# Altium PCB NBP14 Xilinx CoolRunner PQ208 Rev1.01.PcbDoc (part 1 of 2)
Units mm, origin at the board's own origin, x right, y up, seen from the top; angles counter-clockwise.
Board outline 69 x 80.99 mm, 2 copper layers (Top Layer, Bottom Layer); 33 components, 179 nets, 478 pads, 87 vias.
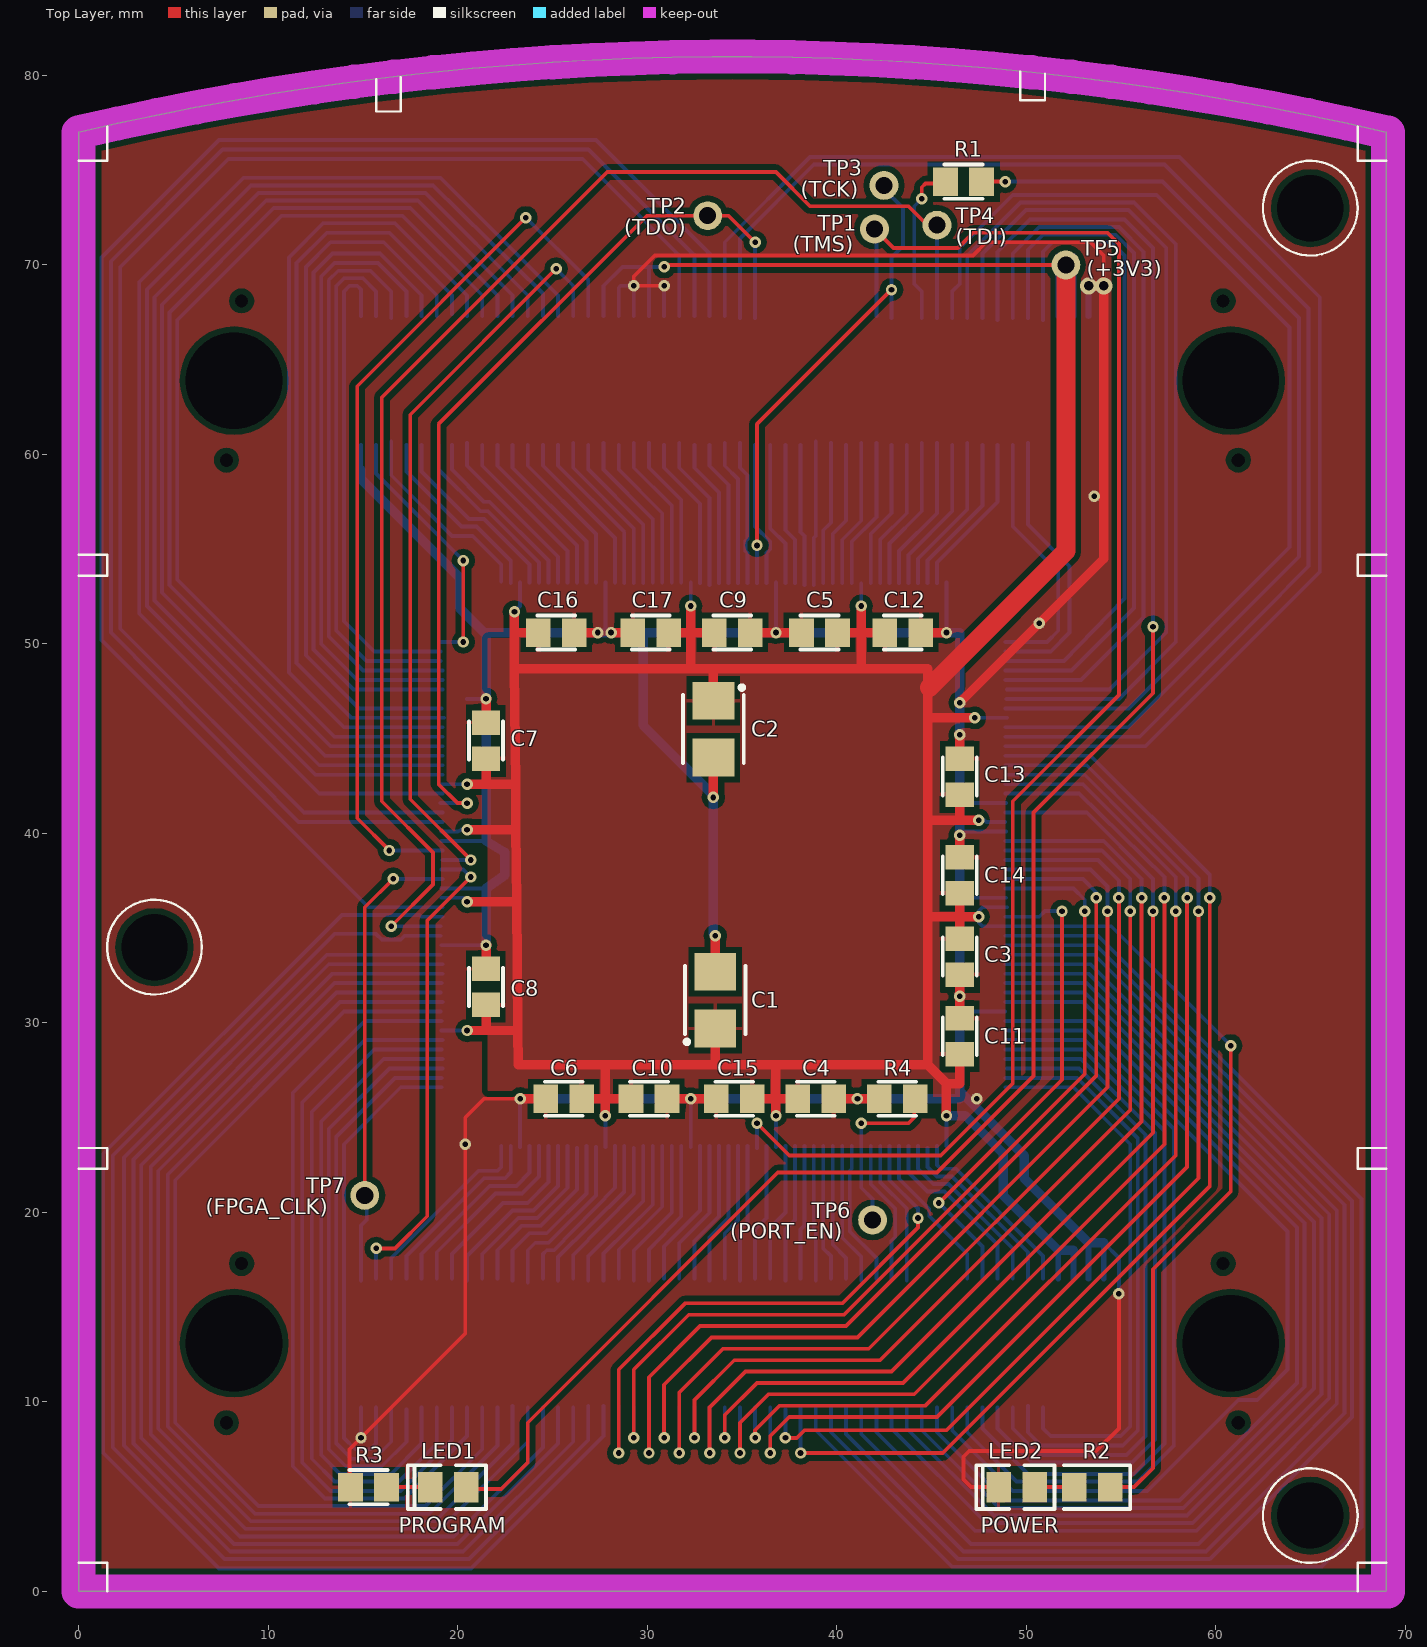
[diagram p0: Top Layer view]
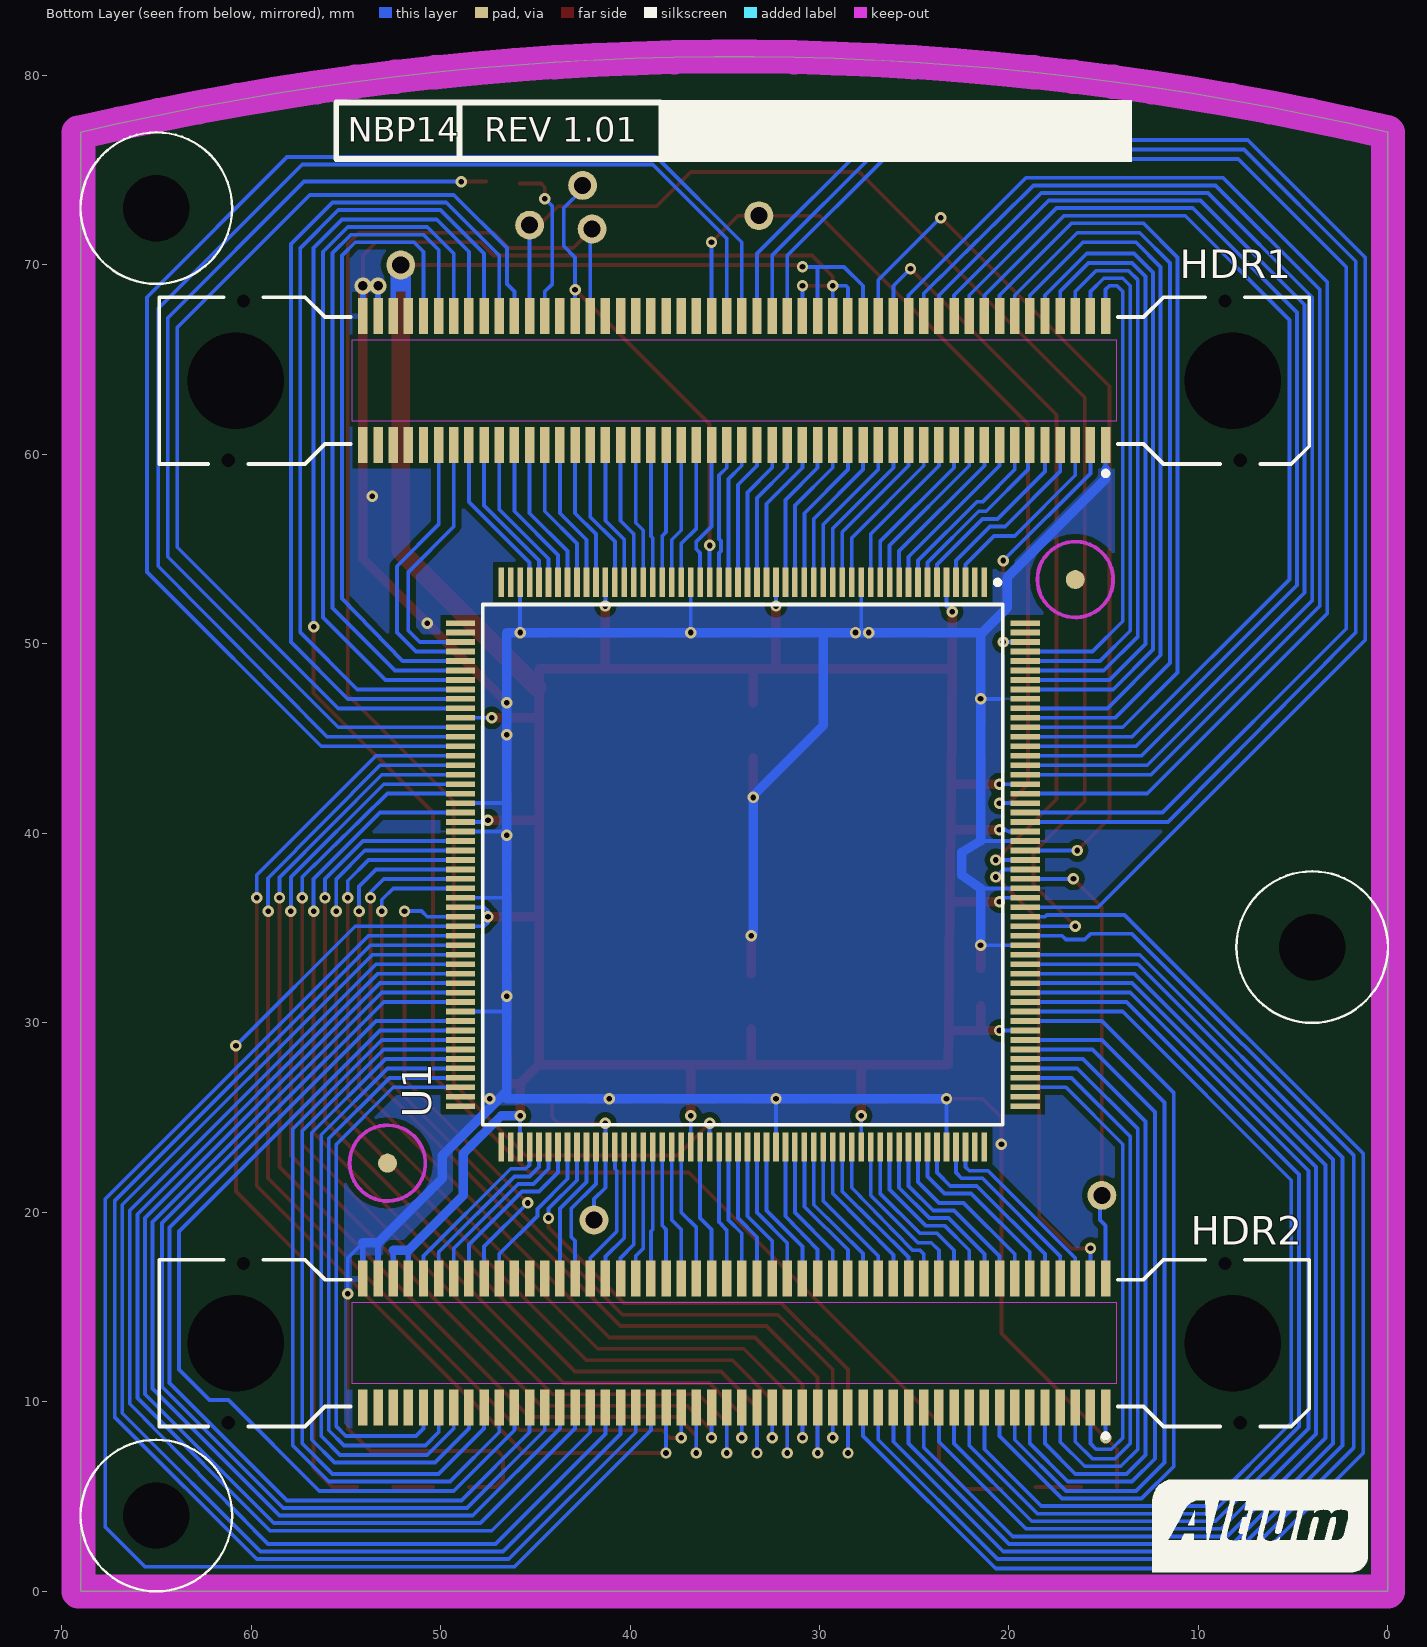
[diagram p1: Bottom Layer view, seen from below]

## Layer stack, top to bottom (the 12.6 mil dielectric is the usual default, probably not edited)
Top Layer: signal copper 0.0356
Dielectric: core 0.32, FR-4, Dk 4.8
Bottom Layer: signal copper 0.0356

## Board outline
0,0 0.001,77 cw(c34.5,-69.801) 69,77 69,0

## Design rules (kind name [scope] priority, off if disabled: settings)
Clearance Clearance_Polygons [InPolygon] p1: gap=0.3
Clearance [All] p2: gap=0.2
ComponentClearance [All] p1: gap=0.2 collisioncheckmode=3 verticalgap=0.254 showdistances=FALSE
FabricationTestPointUsage TestPointUsage [All] p1 off: valid=0 allowmultiple=FALSE
FabricationTestpoint Testpoint [All] p1 off: side=3 testpointundercomponent=TRUE minsize=1.016 maxsize=2.54 preferedsize=1.524 minholesize=0 maxholesize=1.016 preferedholesize=0.813 testpointgrid=0.025 allowsidetop=TRUE allowsidebottom=TRUE usegrid=TRUE gridtolerance=0
HoleSize [All] p1: absolutevalues=TRUE maxlimit=5.2 minlimit=0.25 maxpercent=80.000 minpercent=20.000
MaximumViaCount [All] p1 off: limit=2
PlaneClearance [All] p1: clearance=0.45
PlaneConnect [All] p1: planeconnectstyle=Direct reliefexpansion=0.5 reliefentries=4 reliefconductorwidth=0.25 reliefairgap=0.25
PolygonConnect [All] p1: connectstyle=Relief reliefconductorwidth=0.2 reliefentries=4 polygonreliefangle="90 Angle"
RoutingVias [All] p1: holewidth=0.3 width=0.6 viastyle="Through Hole" minholewidth=0.3 minwidth=0.6 maxholewidth=0.5 maxwidth=1.4
SMDNeckDown [All] p1: percent=80.000
SilkscreenOverComponentPads [All] p1: minsilkscreentomaskgap=0.254
SolderMaskExpansion SolderMaskExpansion_Vias [IsVia] p1: expansion=-0.15
SolderMaskExpansion [All] p2: expansion=0.15
Width [All] p1: maxlimit=1.4 minlimit=0.2 preferedwidth=0.2
21 further rules are at their usual default settings.

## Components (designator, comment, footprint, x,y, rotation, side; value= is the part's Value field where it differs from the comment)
C1 "10uF" MCCT-B 33.6,31.2 r90 top
C2 "10uF" MCCT-B 33.5,45.5 r270 top
C3 "0.1uF" CC2012-0805 46.5,33.5 r270 top
C4 "0.1uF" CC2012-0805 38.9,26 r0 top
C5 "0.1uF" CC2012-0805 39.1,50.6 r180 top
C6 "0.1uF" CC2012-0805 25.6,26 r180 top
C7 "0.1uF" CC2012-0805 21.5,44.9 r90 top
C8 "0.1uF" CC2012-0805 21.5,31.9 r90 top
C9 "0.1uF" CC2012-0805 34.5,50.6 r0 top
C10 "0.1uF" CC2012-0805 30.1,26 r0 top
C11 "0.1uF" CC2012-0805 46.5,29.3 r90 top
C12 "0.1uF" CC2012-0805 43.5,50.6 r0 top
C13 "0.1uF" CC2012-0805 46.5,43 r90 top
C14 "0.1uF" CC2012-0805 46.5,37.8 r90 top
C15 "0.1uF" CC2012-0805 34.6,26 r180 top
C16 "0.1uF" CC2012-0805 25.2,50.6 r0 top
C17 "0.1uF" CC2012-0805 30.2,50.6 r180 top
HDR1 "54075-1009-HD1" 54075 34.5,63.9 r0 bottom locked
HDR2 "54075-1009-HD2" 54075 34.5,13.1 r0 bottom locked
LED1 "HSMG-C170" "SMD _LED" 19.5,5.5 r0 top locked
LED2 "HSMH-C170" "SMD _LED" 49.5,5.5 r0 top locked
R1 "100R" CC2012-0805 46.7,74.4 r0 top
R2 "270R" CC2012-0805 53.5,5.5 r180 top
R3 "270R" CC2012-0805 15.3,5.5 r0 top
R4 "4K7" CC2012-0805 43.2,26 r0 top
TP1 "(TMS)" TestPin 42,71.9 r90 top
TP2 "(TDO)" TestPin 33.2,72.6 r90 top
TP3 "(TCK)" TestPin 42.5,74.2 r90 top
TP4 "(TDI)" TestPin 45.3,72.1 r90 top
TP5 "(+3V3)" TestPin 52.1,70 r90 top
TP6 "(PORT_EN)" TestPin 41.9,19.6 r90 top
TP7 "(FPGA_CLK)" TestPin 15.1,20.9 r90 top
U1 "XCR3256XL-10PQ208C" PQ208 34.05,38.35 r270 bottom locked

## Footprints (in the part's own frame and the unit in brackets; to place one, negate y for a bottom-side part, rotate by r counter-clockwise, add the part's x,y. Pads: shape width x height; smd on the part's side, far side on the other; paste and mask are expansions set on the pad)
54075 [mm] "Connector; Docking Station, Receptacle; 100 Position; Vertical"
  rect 0.5x1.9 smd: 1(-19.6,3.4) 2(-19.6,-3.4) 3(-18.8,3.4) 4(-18.8,-3.4) 5(-18,3.4) 6(-18,-3.4) 7(-17.2,3.4) 8(-17.2,-3.4) 9(-16.4,3.4) 10(-16.4,-3.4) 11(-15.6,3.4) 12(-15.6,-3.4) 13(-14.8,3.4) 14(-14.8,-3.4) 15(-14,3.4) 16(-14,-3.4) 17(-13.2,3.4) 18(-13.2,-3.4) 19(-12.4,3.4) 20(-12.4,-3.4) 21(-11.6,3.4) 22(-11.6,-3.4) 23(-10.8,3.4) 24(-10.8,-3.4) 25(-10,3.4) 26(-10,-3.4) 27(-9.2,3.4) 28(-9.2,-3.4) 29(-8.4,3.4) 30(-8.4,-3.4) 31(-7.6,3.4) 32(-7.6,-3.4) 33(-6.8,3.4) 34(-6.8,-3.4) 35(-6,3.4) 36(-6,-3.4) 37(-5.2,3.4) 38(-5.2,-3.4) 39(-4.4,3.4) 40(-4.4,-3.4) 41(-3.6,3.4) 42(-3.6,-3.4) 43(-2.8,3.4) 44(-2.8,-3.4) 45(-2,3.4) 46(-2,-3.4) 47(-1.2,3.4) 48(-1.2,-3.4) 49(-0.4,3.4) 50(-0.4,-3.4) 51(0.4,3.4) 52(0.4,-3.4) 53(1.2,3.4) 54(1.2,-3.4) 55(2,3.4) 56(2,-3.4) 57(2.8,3.4) 58(2.8,-3.4) 59(3.6,3.4) 60(3.6,-3.4) 61(4.4,3.4) 62(4.4,-3.4) 63(5.2,3.4) 64(5.2,-3.4) 65(6,3.4) 66(6,-3.4) 67(6.8,3.4) 68(6.8,-3.4) 69(7.6,3.4) 70(7.6,-3.4) 71(8.4,3.4) 72(8.4,-3.4) 73(9.2,3.4) 74(9.2,-3.4) 75(10,3.4) 76(10,-3.4) 77(10.8,3.4) 78(10.8,-3.4) 79(11.6,3.4) 80(11.6,-3.4) 81(12.4,3.4) 82(12.4,-3.4) 83(13.2,3.4) 84(13.2,-3.4) 85(14,3.4) 86(14,-3.4) 87(14.8,3.4) 88(14.8,-3.4) 89(15.6,3.4) 90(15.6,-3.4) 91(16.4,3.4) 92(16.4,-3.4) 93(17.2,3.4) 94(17.2,-3.4) 95(18,3.4) 96(18,-3.4) 97(18.8,3.4) 98(18.8,-3.4) 99(19.6,3.4) 100(19.6,-3.4)
  round 0.5 hole 0.7 unplated: MH1(-26.7,4.2) MH2(-25.9,-4.2) MH3(26.7,4.2) MH4(25.9,-4.2)
  round 4.8 hole 5.1 unplated: MH5(-26.3,0) MH6(26.3,0)
  Top Layer keep-out region: -20.15,2.15 20.15,2.15 20.15,-2.15 -20.15,-2.15
  silkscreen extent -30.35,-4.4 30.35,5.02
CC2012-0805 [mm]
  rect 1.3x1.5 smd: 1(-0.95,0) 2(0.95,0)
  silkscreen extent -1,-0.9 1,0.9
MCCT-B [mm]
  rect 2x2.2 smd: 1(-1.5,0) 2(1.5,0)
  silkscreen extent -2.3,-1.6 1.8,1.6
PQ208 [mm] "208-Pin Plastic Quad Flat Pack (PQ208)"
  rect 1.55x0.3 smd: 1(-14.9,12.75) 2(-14.9,12.25) 3(-14.9,11.75) 4(-14.9,11.25) 5(-14.9,10.75) 6(-14.9,10.25) 7(-14.9,9.75) 8(-14.9,9.25) 9(-14.9,8.75) 10(-14.9,8.25) 11(-14.9,7.75) 12(-14.9,7.25) 13(-14.9,6.75) 14(-14.9,6.25) 15(-14.9,5.75) 16(-14.9,5.25) 17(-14.9,4.75) 18(-14.9,4.25) 19(-14.9,3.75) 20(-14.9,3.25) 21(-14.9,2.75) 22(-14.9,2.25) 23(-14.9,1.75) 24(-14.9,1.25) 25(-14.9,0.75) 26(-14.9,0.25) 27(-14.9,-0.25) 28(-14.9,-0.75) 29(-14.9,-1.25) 30(-14.9,-1.75) 31(-14.9,-2.25) 32(-14.9,-2.75) 33(-14.9,-3.25) 34(-14.9,-3.75) 35(-14.9,-4.25) 36(-14.9,-4.75) 37(-14.9,-5.25) 38(-14.9,-5.75) 39(-14.9,-6.25) 40(-14.9,-6.75) 41(-14.9,-7.25) 42(-14.9,-7.75) 43(-14.9,-8.25) 44(-14.9,-8.75) 45(-14.9,-9.25) 46(-14.9,-9.75) 47(-14.9,-10.25) 48(-14.9,-10.75) 49(-14.9,-11.25) 50(-14.9,-11.75) 51(-14.9,-12.25) 52(-14.9,-12.75) 105(14.9,-12.75) 106(14.9,-12.25) 107(14.9,-11.75) 108(14.9,-11.25) 109(14.9,-10.75) 110(14.9,-10.25) 111(14.9,-9.75) 112(14.9,-9.25) 113(14.9,-8.75) 114(14.9,-8.25) 115(14.9,-7.75) 116(14.9,-7.25) 117(14.9,-6.75) 118(14.9,-6.25) 119(14.9,-5.75) 120(14.9,-5.25) 121(14.9,-4.75) 122(14.9,-4.25) 123(14.9,-3.75) 124(14.9,-3.25) 125(14.9,-2.75) 126(14.9,-2.25) 127(14.9,-1.75) 128(14.9,-1.25) 129(14.9,-0.75) 130(14.9,-0.25) 131(14.9,0.25) 132(14.9,0.75) 133(14.9,1.25) 134(14.9,1.75) 135(14.9,2.25) 136(14.9,2.75) 137(14.9,3.25) 138(14.9,3.75) 139(14.9,4.25) 140(14.9,4.75) 141(14.9,5.25) 142(14.9,5.75) 143(14.9,6.25) 144(14.9,6.75) 145(14.9,7.25) 146(14.9,7.75) 147(14.9,8.25) 148(14.9,8.75) 149(14.9,9.25) 150(14.9,9.75) 151(14.9,10.25) 152(14.9,10.75) 153(14.9,11.25) 154(14.9,11.75) 155(14.9,12.25) 156(14.9,12.75)
  rect 0.3x1.55 smd: 53(-12.75,-14.9) 54(-12.25,-14.9) 55(-11.75,-14.9) 56(-11.25,-14.9) 57(-10.75,-14.9) 58(-10.25,-14.9) 59(-9.75,-14.9) 60(-9.25,-14.9) 61(-8.75,-14.9) 62(-8.25,-14.9) 63(-7.75,-14.9) 64(-7.25,-14.9) 65(-6.75,-14.9) 66(-6.25,-14.9) 67(-5.75,-14.9) 68(-5.25,-14.9) 69(-4.75,-14.9) 70(-4.25,-14.9) 71(-3.75,-14.9) 72(-3.25,-14.9) 73(-2.75,-14.9) 74(-2.25,-14.9) 75(-1.75,-14.9) 76(-1.25,-14.9) 77(-0.75,-14.9) 78(-0.25,-14.9) 79(0.25,-14.9) 80(0.75,-14.9) 81(1.25,-14.9) 82(1.75,-14.9) 83(2.25,-14.9) 84(2.75,-14.9) 85(3.25,-14.9) 86(3.75,-14.9) 87(4.25,-14.9) 88(4.75,-14.9) 89(5.25,-14.9) 90(5.75,-14.9) 91(6.25,-14.9) 92(6.75,-14.9) 93(7.25,-14.9) 94(7.75,-14.9) 95(8.25,-14.9) 96(8.75,-14.9) 97(9.25,-14.9) 98(9.75,-14.9) 99(10.25,-14.9) 100(10.75,-14.9) 101(11.25,-14.9) 102(11.75,-14.9) 103(12.25,-14.9) 104(12.75,-14.9) 157(12.75,14.9) 158(12.25,14.9) 159(11.75,14.9) 160(11.25,14.9) 161(10.75,14.9) 162(10.25,14.9) 163(9.75,14.9) 164(9.25,14.9) 165(8.75,14.9) 166(8.25,14.9) 167(7.75,14.9) 168(7.25,14.9) 169(6.75,14.9) 170(6.25,14.9) 171(5.75,14.9) 172(5.25,14.9) 173(4.75,14.9) 174(4.25,14.9) 175(3.75,14.9) 176(3.25,14.9) 177(2.75,14.9) 178(2.25,14.9) 179(1.75,14.9) 180(1.25,14.9) 181(0.75,14.9) 182(0.25,14.9) 183(-0.25,14.9) 184(-0.75,14.9) 185(-1.25,14.9) 186(-1.75,14.9) 187(-2.25,14.9) 188(-2.75,14.9) 189(-3.25,14.9) 190(-3.75,14.9) 191(-4.25,14.9) 192(-4.75,14.9) 193(-5.25,14.9) 194(-5.75,14.9) 195(-6.25,14.9) 196(-6.75,14.9) 197(-7.25,14.9) 198(-7.75,14.9) 199(-8.25,14.9) 200(-8.75,14.9) 201(-9.25,14.9) 202(-9.75,14.9) 203(-10.25,14.9) 204(-10.75,14.9) 205(-11.25,14.9) 206(-11.75,14.9) 207(-12.25,14.9) 208(-12.75,14.9)
  silkscreen extent -15.03,-13.72 13.73,13.73
"SMD _LED" [mm]
  rect 1.3x1.6 smd: 1(0.95,0) 2(-0.95,0)
  silkscreen extent -2.13,-1.15 2,1.15
TestPin [mil] "SingleTest Pin"
  round 60 hole 35.43: 1(0,0)

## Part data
C1 C2: library part CAP_POLAR, "Polar Capacitor"
C3 C4 C5 C6 C7 C8 C9 C10 C11 C12 C13 C14 C15 C16 C17: library part CAP, "Capacitor"
HDR1 HDR2: "Board-to-Board, Docking Station, 0.80mm (.031\") Pitch, Shielded Receptacle, Vertical, Ultra Low Profile, SMT"
LED1 LED2: library part HSMX-C670, "Typical RED GaAs SMD LED Agilent make"
R1 R2 R3 R4: library part RES, "Resistor"
TP1 TP2 TP3 TP4 TP5 TP6 TP7: library part TestPin
U1: "XCR3256XL CoolRunner XPLA3, 3.3 Volt, 256 Macrocell CPLD, 208-Pin PQFP, Commercial Grade"

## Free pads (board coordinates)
  round 1 smd far side mask+1.5: FD3(16.5,53.4) FD3(52.8,22.6)
  round 3.2 hole 3.5 unplated: LP(4,34) LP(65,4) LP(65,73)

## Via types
v1: diameter 0.6, hole 0.3, Top Layer to Bottom Layer, tented both sides, 85 vias
v2: diameter 0.9, hole 0.5, Top Layer to Bottom Layer, tented both sides, 2 vias

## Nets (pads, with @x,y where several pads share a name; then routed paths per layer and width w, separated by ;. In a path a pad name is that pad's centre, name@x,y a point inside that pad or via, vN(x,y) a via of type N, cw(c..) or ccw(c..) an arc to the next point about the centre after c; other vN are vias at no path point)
AUDIO_SPI_CSN: HDR1.11 U1.7 | length 9.7
  Bottom Layer w0.2: HDR1.11@19,60.5 19,59.2 21.2,57 21.6,57 24.3,54.3 U1.7@24.3,53.25
BLUE0: HDR1.14 U1.198 | length 41.3
  Bottom Layer w0.2: U1.198@19.3,46.1 14.4,46.1 11.5,49 11.5,70.1 13.1,71.7 16.4,71.7 19.7,68.4 HDR1.14@19.7,67.4
BLUE1: HDR1.16 U1.197 | length 44
  Bottom Layer w0.2: U1.197@19.2,45.6 14,45.6 11.1,48.5 11.1,70.4 12.9,72.2 16.7,72.2 20.5,68.4 HDR1.16@20.5,67.3
BOC_CTS: HDR1.13 U1.8 | length 9.5
  Bottom Layer w0.2: HDR1.13@19.7,60.5 19.7,59.2 21.4,57.5 21.7,57.5 24.8,54.4 U1.8@24.8,53.25
BOC_RTS: HDR1.17 U1.10 | length 9.1
  Bottom Layer w0.2: HDR1.17@21.3,60.5 21.3,59.4 25.8,54.9 U1.10@25.8,53.25
BOC_RX: HDR1.19 U1.11 | length 9
  Bottom Layer w0.2: HDR1.19@22.1,60.5 22.1,59.4 26.3,55.2 U1.11@26.3,53.25
BOC_TX: HDR1.15 U1.9 | length 9.3
  Bottom Layer w0.2: HDR1.15@20.5,60.6 HDR1.15@20.5,60.5 20.5,59.4 25.3,54.6 U1.9@25.3,53.25
BUZZER: HDR2.24 U1.144 | length 9.1
  Bottom Layer w0.2: HDR2.24@23.7,16.3 23.7,18 24.1,18.4 24.8,18.4 27.3,20.9 U1.144@27.3,23.45
CAN_RXD: HDR1.4 U1.204 | length 28.2
  Bottom Layer w0.2: HDR1.4@15.7,67.3 15.7,68.6 15,69.3 14,69.3 13.6,68.9 13.6,50.7 15.2,49.1 U1.204@19.1,49.1
CAN_TXD: HDR1.2 U1.205 | length 25.7
  Bottom Layer w0.2: HDR1.2@14.9,67.3 14.9,68.7 14.7,68.9 14.3,68.9 14,68.6 14,51.2 15.6,49.6 U1.205@19.1,49.6
FPGA_AUX0: HDR1.86 LED1.1 | length 99.7
  Top Layer w0.2: LED1.1@20.4,5.4 22.3,5.4 23.7,6.8 23.7,8.9 36.9,22.1 45.3,22.1 50.4,27.2 50.4,41.1 56.7,47.4 v1(56.7,50.9)
  Bottom Layer w0.2: HDR1.86@48.5,67.1 48.5,70.7 50.2,72.4 55.2,72.4 56.7,70.9 v1(56.7,50.9)
FPGA_AUX1: HDR1.88 U1.59 | length 39.4
  Bottom Layer w0.2: U1.59@48.9,48.1 52.9,48.1 56.2,51.4 56.2,70.7 54.9,72 50.7,72 49.3,70.6 HDR1.88@49.3,67.2
FPGA_AUX2: HDR1.90 U1.58 | length 36.8
  Bottom Layer w0.2: U1.58@48.9,48.6 52.4,48.6 55.7,51.9 55.7,70.634 54.734,71.6 50.9,71.6 50.1,70.8 HDR1.90@50.1,67.2
FPGA_AUX3: HDR1.92 U1.57 | length 34.2
  Bottom Layer w0.2: U1.57@48.9,49.1 52,49.1 55.2,52.4 55.2,70.5 54.5,71.2 51.4,71.2 50.9,70.7 HDR1.92@50.9,67.3 HDR1.92@50.9,67.1
FPGA_CCLK: HDR1.66
FPGA_CLK: HDR2.2 TP7.1 U1.181 | length 24.6
  Top Layer w0.2: TP7.1@15.1,20.9 15.1,36.1 v1(16.6,37.6)
  Bottom Layer w0.2: HDR2.2@14.9,16.4 14.9,19.3 15.2,19.6 TP7.1@15.2,21 ; v1(16.6,37.6) U1.181@19.2,37.6
FPGA_CLK_1: HDR1.30 U1.183 | length 40.1
  Top Layer w0.2: v1(20.7,38.6) 17.5,41.8 17.5,62.1 v1(25.2,69.8)
  Bottom Layer w0.2: U1.183@19.2,38.6 v1(20.7,38.6) ; v1(25.2,69.8) 26.1,68.9 HDR1.30@26.1,67.3
FPGA_CLK_2: HDR1.32 U1.184 | length 47.2
  Top Layer w0.2: v1(16.4,39.1) 14.7,40.8 14.7,63.6 v1(23.6,72.5)
  Bottom Layer w0.2: v1(16.4,39.1) U1.184@19.2,39.1 ; v1(23.6,72.5) 26.9,69.2 HDR1.32@26.9,67.3
FPGA_DIN: HDR1.64
FPGA_DONE: HDR1.74
FPGA_INIT: HDR1.68
FPGA_M0: HDR1.60
FPGA_M1: HDR1.58
FPGA_M2: HDR1.56
FPGA_PROGRAM: HDR1.62
FPGA_TCK: HDR1.72 TP3.1 U1.30 | length 25.9
  Top Layer w0.2: v1(35.8,55.2) 35.8,61.6 v1(42.9,68.7)
  Bottom Layer w0.2: U1.30@35.8,53.2 v1(35.8,55.2) ; TP3.1@42.5,74 43.5,73 43.5,71 42.9,70.4 HDR1.72@42.9,67.2
FPGA_TDI: HDR1.78 TP4.1 U1.176 | length 72.8
  Top Layer w0.2: v1(16.5,35.1) 18.7,37.3 18.7,39 16,41.7 16,63 27.9,74.9 36.8,74.9 38.6,73.1 43.8,73.1 44.8,72.1 TP4.1@45.3,72.1
  Bottom Layer w0.2: v1(16.5,35.1) U1.176@19.1,35.1 ; HDR1.78@45.3,67.2 TP4.1@45.3,72.1
FPGA_TDO: HDR1.54 TP2.1 U1.189 | length 48.2
  Top Layer w0.2: v1(20.5,41.6) 20,41.6 19,42.6 19,61.6 30,72.6 34.3,72.6 v1(35.7,71.2)
  Bottom Layer w0.2: U1.189@19.1,41.6 v1(20.5,41.6) ; HDR1.54@35.7,67.2 v1(35.7,71.2)
FPGA_TMS: HDR1.70 TP1.1 U1.127 | length 82.3
  Top Layer w0.2: v1(35.8,24.7) 37.5,23 45.5,23 49.3,26.8 49.3,41.7 54.9,47.3 54.9,71.1 54.3,71.7 47.2,71.7 46.4,70.9 43,70.9 TP1.1@42,71.9
  Bottom Layer w0.2: U1.127@35.8,23.4 v1(35.8,24.7) ; HDR1.70@42.1,67.3 TP1.1@42.1,72
GND: C1.2 C2.2 C3.2 C4.2 C5.2 C6.2 C7.2 C8.2 C9.2 C10.2 C11.2 C12.2 C13.2 C14.2 C15.2 C16.2 C17.2 HDR1.1 HDR1.36 HDR1.38 HDR1.42 HDR1.98 HDR1.100 HDR2.1 HDR2.98 HDR2.100 LED2.2 R3.1 R4.1 U1.14 U1.32 U1.50 U1.72 U1.75 U1.82 U1.94 U1.134 U1.152 U1.174 U1.180 U1.185 U1.200 | length 304.5
  Top Layer w0.2: R3.1@14.3,5.5 14.3,7.5 20.4,13.6 20.4,25 21.4,26 v1(23.3,26) ; v1(30.9,68.9) v1(29.3,68.9) 29.3,69.4 30.4,70.5 47.2,70.5 47.9,71.2 53.4,71.2 54.1,70.5 v2(54.1,68.9) ; LED2.2@48.5,5.5 47.1,5.5 46.7,5.9 46.7,7.1 47,7.4 53.7,7.4 54.9,8.6 v1(54.9,15.7)
  Top Layer w0.5: C8.2@21.5,32.85 v1(21.5,34.1) ; C7.2@21.5,45.85 v1(21.5,47.1) ; v1(23.3,26) C6.2@24.6,26 ; C16.2@26.1,50.6 v1(27.4,50.6) ; v1(28.1,50.6) C17.2@29.2,50.6 ; C10.2@31,26 C15.2@33.6,26 ; v1(33.5,41.9) C2.2@33.5,44 ; C1.2@33.6,32.6 v1(33.6,34.6) ; C9.2@35.3,50.6 v1(36.8,50.6) C5.2@38.2,50.6 ; C4.2@40,26 R4.1@42.2,26 ; C12.2@44.4,50.6 v1(45.8,50.6) ; C11.2@46.5,30.2 C3.2@46.5,32.6 ; C14.2@46.5,38.7 v1(46.5,39.9) ; C13.2@46.5,43.9 v1(46.5,45.2) ; v1(46.5,46.9) 54.1,54.5 v2(54.1,68.9) v2(53.3,68.9)
  Bottom Layer w0.2: v1(14.9,8.1) HDR2.1@14.9,9.7 ; 14.9,59.1 HDR1.1@14.9,60.5 ; U1.174@19.15,34.1 v1(21.5,34.1) ; U1.180@19.15,37.1 21.5,37.1 ; U1.185@19.15,39.6 21.5,39.6 ; 20.5,47.1 v1(21.5,47.1) ; U1.152@23.3,23.45 v1(23.3,26) ; v1@27.8,50.6 U1.14@27.8,53.25 ; HDR1.36@28.5,67.3 28.5,68.8 28.6,68.9 v1(29.3,68.9) HDR1.38@29.3,67.3 ; HDR1.42@30.9,67.3 v1(30.9,68.9) ; U1.134@32.3,23.45 v1(32.3,26) ; v1(36.8,50.6) U1.32@36.8,53.25 ; v1(45.8,50.6) U1.50@45.8,53.25 ; 46.5,30.6 U1.94@48.9,30.6 ; 46.5,36.6 U1.82@48.95,36.6 ; v1@46.5,40.1 U1.75@48.95,40.1 ; 46.5,41.6 U1.72@48.95,41.6 ; 54.1,18.4 54.9,17.6 v1(54.9,15.7)
  Bottom Layer w0.3: HDR2.98@53.3,16.5 53.3,18.4 ; HDR1.98@53.3,67.3 v2@53.3,68.8 ; HDR2.100@54.1,16.5 54.1,18.4 ; HDR1.100@54.1,67.3 v2(54.1,68.9)
  Bottom Layer w0.5: 14.9,59.2 14.9,58.7 20.1,53.5 20.1,51.9 21.5,50.5 ; v1(21.5,34.1) 21.5,37.1 22.5,37.8 22.5,39 21.5,39.6 21.5,50.6 46.5,50.6 46.5,26 v1(23.3,26) ; 29.8,50.6 29.8,45.7 33.5,42 33.5,34.7 v1(33.6,34.6) ; 46.5,26.4 49.9,23 49.9,21.8 53.3,18.4 54.1,18.4
  other v1: 20.4,23.6 41.1,26 47.4,26 46.5,31.4 50.7,51.1 53.6,57.8
GREEN0: HDR1.10 U1.201 | length 35.7
  Bottom Layer w0.2: HDR1.10@18.1,67.3 18.1,68.4 15.9,70.6 13.4,70.6 12.4,69.6 12.4,49.7 14.5,47.6 U1.201@19.2,47.6
GREEN1: HDR1.12 U1.199 | length 38.5
  Bottom Layer w0.2: HDR1.12@18.9,67.3 18.9,68.4 16.1,71.2 13.3,71.2 12,69.9 12,49.4 14.8,46.6 U1.199@19.15,46.6
HDRIVE: HDR1.18 U1.196 | length 52.4
  Bottom Layer w0.2: U1.196@19.2,45.1 13.5,45.1 5.2,53.4 5.2,67.1 10.7,72.6 17.1,72.6 21.3,68.4 HDR1.18@21.3,67.3
IO0: HDR2.7 U1.161 | length 30.9
  Bottom Layer w0.2: HDR2.7@17.3,9.6 17.3,7.9 16,6.6 14.1,6.6 13.2,7.5 13.2,24.4 16.4,27.6 U1.161@19.2,27.6
IO1: HDR2.9 U1.162 | length 33.6
  Bottom Layer w0.2: HDR2.9@18.1,9.7 18.1,7.8 16.5,6.2 13.8,6.2 12.8,7.2 12.8,24.8 16.1,28.1 U1.162@19.2,28.1
IO2: HDR2.11 U1.163 | length 36.3
  Bottom Layer w0.2: HDR2.11@18.9,9.7 18.9,7.8 16.9,5.8 13.5,5.8 12.3,7 12.3,25.3 15.6,28.6 U1.163@19.15,28.6
IO3: HDR2.13 U1.164 | length 39.1
  Bottom Layer w0.2: U1.164@19.2,29.1 15.1,29.1 11.8,25.8 11.8,6.8 13.3,5.3 17,5.3 19.7,8 HDR2.13@19.7,9.7
IO4: HDR2.15 U1.166 | length 41.9
  Bottom Layer w0.2: U1.166@19.15,30.1 15.1,30.1 11.3,26.3 11.3,6.6 13,4.9 17.2,4.9 20.5,8.2 HDR2.15@20.5,9.7
IO5: HDR2.17 U1.167 | length 52
  Bottom Layer w0.2: U1.167@19.1,30.6 14,30.6 5.1,21.7 5.1,8.9 9.5,4.5 18.3,4.5 21.3,7.5 HDR2.17@21.3,9.7
IO6: HDR2.19 U1.168 | length 54.4
  Bottom Layer w0.2: U1.168@19.2,31.1 13.8,31.1 4.7,22 4.7,8.7 9.3,4.1 18.5,4.1 22.1,7.7 HDR2.19@22.1,9.7
IO7: HDR2.21 U1.169 | length 56.8
  Bottom Layer w0.2: U1.169@19.1,31.6 13.6,31.6 4.2,22.2 4.2,8.6 9.1,3.7 18.8,3.7 22.9,7.8 HDR2.21@22.9,9.8
IO8: HDR2.23 U1.170 | length 59.1
  Bottom Layer w0.2: U1.170@19.15,32.1 13.5,32.1 3.8,22.4 3.8,8.3 8.8,3.3 19.1,3.3 23.7,7.9 HDR2.23@23.7,9.7
IO9: HDR2.25 U1.171 | length 61.9
  Bottom Layer w0.2: U1.171@19.2,32.6 13.4,32.6 3.3,22.5 3.3,8.1 8.5,2.9 19.8,2.9 24.5,7.6 HDR2.25@24.5,9.7
IO10: HDR2.27 U1.172 | length 64.3
  Bottom Layer w0.2: U1.172@19.2,33.1 13.2,33.1 2.9,22.8 2.9,7.8 8.2,2.5 20,2.5 25.3,7.8 HDR2.27@25.3,9.7
IO11: HDR2.29 U1.173 | length 66.6
  Bottom Layer w0.2: U1.173@19.1,33.6 13.1,33.6 2.4,22.9 2.4,7.7 8,2.1 20.3,2.1 26.1,7.9 HDR2.29@26.1,9.7
IO12: HDR2.31 U1.175 | length 69.7
  Bottom Layer w0.2: U1.175@19.1,34.6 17.2,34.6 17,34.4 16,34.4 15.7,34.7 13.5,34.7 1.8,23 1.8,7.6 7.7,1.7 20.6,1.7 26.9,8 HDR2.31@26.9,9.8
IO13: HDR2.33 U1.177 | length 72.4
  Bottom Layer w0.2: U1.177@19.2,35.6 18.1,35.6 18,35.7 13.9,35.7 1.3,23.1 1.3,7.3 7.4,1.2 20.7,1.2 27.7,8.2 HDR2.33@27.7,9.8
IO14: HDR2.35 U1.113 | length 30.7
  Top Layer w0.2: v1(28.5,7.3) 28.5,11.7 32,15.2 40.3,15.2 44.3,19.2 v1(44.3,19.7)
  Bottom Layer w0.2: v1(28.5,7.3) HDR2.35@28.5,9.8 ; U1.113@42.8,23.5 42.8,21.7 44.3,20.2 v1(44.3,19.7)
IO15: HDR2.37 U1.81 | length 49.1
  Top Layer w0.2: v1(29.3,8.1) 29.3,11.7 32.2,14.6 40.4,14.6 53.1,27.3 v1(53.1,35.9)
  Bottom Layer w0.2: v1(29.3,8.1) HDR2.37@29.3,9.7 ; U1.81@48.9,37.1 52.5,37.1 53.1,36.5 v1(53.1,35.9)
IO16: HDR2.39 U1.80 | length 51.4
  Top Layer w0.2: v1(30.1,7.3) 30.1,11.3 32.8,14 40.5,14 53.7,27.2 v1(53.7,36.6)
  Bottom Layer w0.2: v1(30.1,7.3) HDR2.39@30.1,9.7 ; U1.80@48.9,37.6 53,37.6 53.7,36.9 v1(53.7,36.6)
IO17: HDR2.41 U1.79 | length 50.7
  Top Layer w0.2: v1(30.9,8.1) 30.9,10.9 33.4,13.4 41.1,13.4 54.3,26.6 v1(54.3,35.9)
  Bottom Layer w0.2: v1(30.9,8.1) HDR2.41@30.9,9.7 ; U1.79@48.9,38.1 53.4,38.1 54.3,37.2 v1(54.3,35.9)
IO18: HDR2.43 U1.78 | length 53.2
  Top Layer w0.2: v1(31.7,7.3) 31.7,10.5 34,12.8 41.7,12.8 54.9,26 v1(54.9,36.6)
  Bottom Layer w0.2: v1(31.7,7.3) HDR2.43@31.7,9.7 ; U1.78@48.9,38.6 53.8,38.6 54.9,37.5 v1(54.9,36.6)
IO19: HDR2.45 U1.77 | length 52.5
  Top Layer w0.2: v1(32.5,8.1) 32.5,10.1 34.6,12.2 42.3,12.2 55.5,25.4 v1(55.5,35.9)
  Bottom Layer w0.2: v1(32.5,8.1) HDR2.45@32.5,9.7 ; U1.77@48.9,39.1 54,39.1 55.5,37.6 v1@55.5,35.8
IO20: HDR2.47 U1.76 | length 54.6
  Top Layer w0.2: v1(33.3,7.3) 33.3,9.7 35.2,11.6 42.9,11.6 56.1,24.8 v1@56.1,36.5
  Bottom Layer w0.2: v1(33.3,7.3) HDR2.47@33.3,9.7 ; U1.76@48.9,39.6 54.1,39.6 56.1,37.6 v1(56.1,36.6)
IO21: HDR2.49 U1.73 | length 54.2
  Top Layer w0.2: v1(34.1,8.1) 34.1,9.3 35.8,11 43.5,11 56.7,24.2 v1(56.7,35.9)
  Bottom Layer w0.2: v1(34.1,8.1) HDR2.49@34.1,9.7 ; U1.73@48.9,41.1 53.2,41.1 56.7,37.6 v1(56.7,35.9)
IO22: HDR2.51 U1.71 | length 56.8
  Top Layer w0.2: v1(34.9,7.3) 34.9,8.9 36.4,10.4 44.1,10.4 57.3,23.6 v1(57.3,36.6)
  Bottom Layer w0.2: v1(34.9,7.3) HDR2.51@34.9,9.7 ; U1.71@48.9,42.1 52.8,42.1 57.3,37.7 v1(57.3,36.6)
IO23: HDR2.53 U1.70 | length 55.9
  Top Layer w0.2: v1(35.7,8.1) 35.7,8.5 37,9.8 44.7,9.8 57.9,23 v1(57.9,35.9)
  Bottom Layer w0.2: v1(35.7,8.1) HDR2.53@35.7,9.7 ; U1.70@48.9,42.6 53,42.6 57.9,37.7 v1(57.9,35.9)
IO24: HDR2.55 U1.69 | length 58.3
  Top Layer w0.2: v1(36.5,7.3) 36.5,8.2 37.5,9.2 45.3,9.2 58.5,22.4 v1(58.5,36.6)
  Bottom Layer w0.2: v1(36.5,7.3) HDR2.55@36.5,9.7 ; U1.69@48.9,43.1 53.1,43.1 58.5,37.669 v1(58.5,36.6)
IO25: HDR2.57 U1.68 | length 57.5
  Top Layer w0.2: v1(37.3,8.1) 37.9,8.1 38.3,8.5 45.8,8.5 59.1,21.8 v1(59.1,35.9)
  Bottom Layer w0.2: v1(37.3,8.1) HDR2.57@37.3,9.6 ; U1.68@48.9,43.6 53.2,43.6 59.1,37.634 v1(59.1,35.9)
IO26: HDR2.59 U1.67 | length 59.6
  Top Layer w0.2: v1(38.1,7.3) 45.6,7.3 59.7,21.4 v1(59.7,36.6)
  Bottom Layer w0.2: v1(38.1,7.3) HDR2.59@38.1,9.7 ; U1.67@48.9,44.1 53.4,44.1 59.7,37.8 v1(59.7,36.6)
IO27: HDR2.61 U1.86 | length 75.7
  Bottom Layer w0.2: HDR2.61@38.9,9.7 38.9,8.5 46.1,1.3 65.6,1.3 67.7,3.4 67.7,20.7 53.8,34.6 U1.86@48.9,34.6
IO28: HDR2.63 U1.87 | length 70
  Bottom Layer w0.2: HDR2.63@39.7,9.7 39.7,8.4 46.4,1.7 59.7,1.7 67.2,9.2 67.2,20.6 53.7,34.1 U1.87@48.9,34.1
IO29: HDR2.65 U1.88 | length 67.7
  Bottom Layer w0.2: HDR2.65@40.5,9.7 40.5,8.3 46.7,2.1 59.5,2.1 66.8,9.4 66.8,20.4 53.6,33.6 U1.88@48.9,33.6
IO30: HDR2.67 U1.89 | length 65.2
  Bottom Layer w0.2: HDR2.67@41.3,9.8 HDR2.67@41.3,9.7 41.3,8.3 47.1,2.5 59.1,2.5 66.4,9.9 66.4,20.1 53.4,33.1 U1.89@48.9,33.1
IO31: HDR2.69 U1.90 | length 62.4
  Bottom Layer w0.2: HDR2.69@42.1,9.8 42.1,8.4 47.3,3.2 59,3.2 66,10.2 66,19.9 53.3,32.6 U1.90@48.9,32.6
IO32: HDR2.71 U1.91 | length 59.8
  Bottom Layer w0.2: HDR2.71@42.9,9.7 42.9,8.6 47.9,3.6 58.8,3.6 65.6,10.4 65.6,19.7 53.2,32.1 U1.91@48.9,32.1
IO33: HDR2.73 U1.92 | length 57.4
  Bottom Layer w0.2: HDR2.73@43.7,9.7 43.7,8.6 48.3,4 58.5,4 65.2,10.7 65.2,19.5 53.1,31.6 U1.92@48.9,31.6
IO34: HDR2.75 U1.93 | length 55.1
  Bottom Layer w0.2: HDR2.75@44.5,9.8 44.5,8.5 48.6,4.4 58.3,4.4 64.7,10.8 64.7,19.434 53,31.1 U1.93@48.9,31.1
IO35: HDR2.77 U1.95 | length 52.5
  Bottom Layer w0.2: HDR2.77@45.3,9.7 45.3,8.4 48.9,4.8 58.1,4.8 64.3,11 64.3,19.2 53.4,30.1 U1.95@48.9,30.1
JIOA0: HDR1.3 U1.206 | length 14.9
  Top Layer w0.2: v1(20.3,50.1) v1(20.3,54.4)
  Bottom Layer w0.2: 15.7,59.1 HDR1.3@15.7,60.5 15.7,59 v1(20.3,54.4) ; U1.206@19.1,50.1 v1(20.3,50.1)
JIOA1: HDR1.5 U1.3 | length 10.4
  Bottom Layer w0.2: HDR1.5@16.5,60.7 16.5,58.9 19.7,55.7 20.8,55.7 22.3,54.2 U1.3@22.3,53.3
JIOA2: HDR1.7 U1.4 | length 10
  Bottom Layer w0.2: HDR1.7@17.3,60.5 17.3,59.1 20.2,56.2 21,56.2 22.8,54.4 U1.4@22.8,53.2
JIOA3: HDR1.9 U1.6 | length 10.1
  Bottom Layer w0.2: HDR1.9@18.1,60.5 18.1,59.1 20.6,56.6 21.4,56.6 23.8,54.2 U1.6@23.8,53.25
JIOB0: HDR1.83 U1.48 | length 8.5
  Bottom Layer w0.2: U1.48@44.8,53.2 44.8,54.4 47.7,57.3 HDR1.83@47.7,60.5
JIOB1: HDR1.85 U1.49 | length 8.6
  Bottom Layer w0.2: U1.49@45.3,53.2 45.3,54.3 ; 45.325,54.325 48.5,57.5 HDR1.85@48.5,60.5
JIOB2: HDR1.87 U1.55 | length 13.8
  Bottom Layer w0.2: U1.55@48.9,50.1 51.1,50.1 51.7,50.7 51.7,53.8 49.3,56.2 HDR1.87@49.3,60.5
JIOB3: HDR1.89 U1.56 | length 14.7
  Bottom Layer w0.2: U1.56@48.9,49.6 51.3,49.6 52.3,50.6 52.3,54.1 50.1,56.3 HDR1.89@50.1,60.6
KBCLOCK: HDR1.22 U1.194 | length 57.5
  Bottom Layer w0.2: U1.194@19.2,44.1 13,44.1 4.4,52.7 4.4,67.9 9.9,73.4 17.9,73.4 22.9,68.4 HDR1.22@22.9,67.3
KBDATA: HDR1.24 U1.193 | length 60.1
  Bottom Layer w0.2: U1.193@19.2,43.6 12.7,43.6 4,52.3 4,68.3 9.5,73.8 18.3,73.8 23.7,68.4 HDR1.24@23.7,67.3
LCD_BCKL: HDR2.22 U1.145 | length 9.2
  Bottom Layer w0.2: HDR2.22@22.9,16.4 22.9,18 23.8,18.9 24.7,18.9 26.8,21 U1.145@26.8,23.5
LCD_E: HDR2.26 U1.142 | length 8.8
  Bottom Layer w0.2: HDR2.26@24.5,16.5 24.5,17.8 24.7,18 25.086,18 28.3,21.3 U1.142@28.3,23.5
LED0: HDR2.60 U1.122 | length 7.1
  Bottom Layer w0.2: HDR2.60@38.1,16.5 38.1,19.1 38.3,19.3 U1.122@38.3,23.5
LED1: HDR2.62 U1.121 | length 7.1
  Bottom Layer w0.2: U1.121@38.8,23.5 38.8,19.1 38.9,19 HDR2.62@38.9,16.4
LED2: HDR2.64 U1.120 | length 7.2
  Bottom Layer w0.2: U1.120@39.3,23.5 39.3,18.1 39.7,17.7 HDR2.64@39.7,16.5
LED3: HDR2.66 U1.119 | length 7.3
  Bottom Layer w0.2: U1.119@39.8,23.5 39.8,18.3 40.5,17.6 HDR2.66@40.5,16.5
LED4: HDR2.68 U1.118 | length 7.5
  Bottom Layer w0.2: U1.118@40.3,23.5 40.3,18.666 41.3,17.666 HDR2.68@41.3,16.4
LED5: HDR2.70 U1.117 | length 7.6
  Bottom Layer w0.2: U1.117@40.8,23.5 40.8,22.3 40.7,22.2 40.7,19 42.1,17.6 HDR2.70@42.1,16.5
LED6: HDR2.72 U1.115 | length 7.6
  Bottom Layer w0.2: U1.115@41.8,23.5 41.8,21.5 43.1,20.2 43.1,18.7 42.9,18.5 HDR2.72@42.9,16.5
LED7: HDR2.74 U1.114 | length 7.7
  Bottom Layer w0.2: U1.114@42.3,23.5 42.3,21.6 43.7,20.2 HDR2.74@43.7,16.4
MOUSECLOCK: HDR1.26 U1.192 | length 62.7
  Bottom Layer w0.2: U1.192@19.2,43.1 12.5,43.1 3.6,52 3.6,68.7 9.1,74.2 18.7,74.2 24.5,68.5 HDR1.26@24.5,67.3
MOUSEDATA: HDR1.28 U1.190 | length 65.5
  Bottom Layer w0.2: U1.190@19.2,42.1 12.7,42.1 3.2,51.6 3.2,69.1 8.7,74.6 19.1,74.6 25.3,68.4 HDR1.28@25.3,67.3
NetLED1_2: LED1.2 R3.2 | length 2.4
  Top Layer w0.2: R3.2@16.2,5.5 LED1.2@18.6,5.5
NetLED2_1: LED2.1 R2.2 | length 2.1
  Top Layer w0.2: LED2.1@50.4,5.5 R2.2@52.5,5.5
NetR4_2: R4.2 TP6.1 U1.116 | length 9.3
  Top Layer w0.2: v1(41.3,24.7) 43.8,24.7 44.1,25 R4.2@44.1,26
  Bottom Layer w0.2: v1(41.3,24.7) 41.3,21.3 41.9,20.7 TP6.1@41.9,19.6
NEXUS_TCK: HDR1.82 U1.61 | length 47.6
  Bottom Layer w0.2: HDR1.82@46.9,67.2 46.9,70.5 49.7,73.3 55.7,73.3 57.9,71.1 57.9,50.1 54.9,47.1 U1.61@48.95,47.1
NEXUS_TDI: HDR1.84 U1.60 | length 44.8
  Bottom Layer w0.2: HDR1.84@47.7,67.2 47.7,70.6 50,72.9 55.4,72.9 57.4,70.9 57.4,50.6 54.4,47.6 U1.60@49,47.6
NEXUS_TDO: R1.2 U1.64 | length 51.6
  Top Layer w0.2: R1.2@47.6,74.4 v1(48.9,74.4)
  Bottom Layer w0.2: U1.64@48.9,45.6 55.4,45.6 64.4,54.6 64.4,67.2 57.2,74.4 v1(48.9,74.4)
NEXUS_TDO#: HDR1.76 R1.1 | length 8.6
  Top Layer w0.2: v1(44.5,73.5) 44.5,74.1 44.7,74.3 R1.1@45.8,74.3
  Bottom Layer w0.2: HDR1.76@44.5,67.2 HDR1.76@44.5,67.3 44.5,68.6 44.1,69 44.1,73.1 v1(44.5,73.5)
NEXUS_TMS: HDR1.80 U1.62 | length 55.4
  Bottom Layer w0.2: HDR1.80@46.1,67.2 HDR1.80@46.1,67.3 46.1,68.6 46.5,69 46.5,70.9 49.3,73.7 56.9,73.7 63.9,66.7 63.9,55.1 55.4,46.6 U1.62@48.9,46.6
RAM0_DATA0: HDR2.42 U1.133 | length 7.8
  Bottom Layer w0.2: HDR2.42@30.9,16.5 30.9,18.2 32.8,20.1 U1.133@32.8,23.5
RAM0_DATA1: HDR2.40 U1.135 | length 7.8
  Bottom Layer w0.2: HDR2.40@30.1,16.4 30.1,18.048 31.8,19.8 U1.135@31.8,23.5
RAM0_DATA2: HDR2.38 U1.136 | length 7.9
  Bottom Layer w0.2: HDR2.38@29.3,16.4 29.3,17.987 31.3,20 U1.136@31.3,23.5
RAM0_DATA3: HDR2.36 U1.137 | length 8
  Bottom Layer w0.2: HDR2.36@28.5,16.5 28.5,18.025 30.8,20.3 U1.137@30.8,23.5
RAM0_DATA4: HDR2.34 U1.138 | length 8.2
  Bottom Layer w0.2: HDR2.34@27.7,16.4 27.7,17.836 30.3,20.4 U1.138@30.3,23.5
RAM0_DATA5: HDR2.32 U1.139 | length 8.3
  Bottom Layer w0.2: HDR2.32@26.9,16.4 26.9,17.7 29.8,20.6 U1.139@29.8,23.5
RAM0_DATA6: HDR2.30 U1.140 | length 8.2
  Bottom Layer w0.2: HDR2.30@26.1,16.5 26.1,17.747 29.3,21 U1.140@29.3,23.4
RAM0_DATA7: HDR2.28 U1.141 | length 8.6
  Bottom Layer w0.2: HDR2.28@25.3,16.4 25.3,17.649 28.8,21.1 U1.141@28.8,23.5
RAM0_OE: HDR1.41 U1.24 | length 8.1
  Bottom Layer w0.2: HDR1.41@30.9,60.5 30.9,59.3 32.8,57.4 U1.24@32.8,53.2
RAM0_WE: HDR1.79 U1.46 | length 8.3
  Bottom Layer w0.2: U1.46@43.8,53.2 43.8,54.7 46.1,57 HDR1.79@46.1,60.5
RAM1_DATA0: HDR1.45 U1.26 | length 7.8
  Bottom Layer w0.2: HDR1.45@32.5,60.5 32.5,59.3 33.8,58 U1.26@33.8,53.2
RAM1_DATA1: HDR1.49 U1.28 | length 7.7
  Bottom Layer w0.2: HDR1.49@34.1,60.6 HDR1.49@34.1,60.5 34.1,59.4 34.8,58.7 U1.28@34.8,53.2
RAM1_DATA2: HDR1.53 U1.31 | length 7.7
  Bottom Layer w0.2: HDR1.53@35.7,60.5 35.7,56.2 36.5,55.4 36.5,55 36.3,54.8 U1.31@36.3,53.2
RAM1_DATA3: HDR1.57 U1.34 | length 7.5
  Bottom Layer w0.2: HDR1.57@37.3,60.5 37.3,56 37.8,55.5 U1.34@37.8,53.2
RAM1_DATA4: HDR1.55 U1.33 | length 7.6
  Bottom Layer w0.2: HDR1.55@36.5,60.5 36.5,56.1 37.3,55.3 U1.33@37.3,53.2
RAM1_DATA5: HDR1.51 U1.29 | length 7.6
  Bottom Layer w0.2: HDR1.51@34.9,60.6 HDR1.51@34.9,60.5 34.9,59.3 35.3,58.9 35.3,55.532 35.2,55.432 35.2,54.9 35.3,54.8 U1.29@35.3,53.2
RAM1_DATA6: HDR1.47 U1.27 | length 7.7
  Bottom Layer w0.2: HDR1.47@33.3,60.5 33.3,59.4 34.3,58.4 U1.27@34.3,53.2
RAM1_DATA7: HDR1.43 U1.25 | length 8.2
  Bottom Layer w0.2: HDR1.43@31.7,60.6 31.7,59.3 33.3,57.7 U1.25@33.3,53.1
RAM1_OE: HDR1.39 U1.22 | length 8.1
  Bottom Layer w0.2: HDR1.39@30.1,60.6 HDR1.39@30.1,60.5 30.1,59.3 31.8,57.6 U1.22@31.8,53.25
RAM1_WE: HDR1.61 U1.36 | length 7.6
  Bottom Layer w0.2: U1.36@38.8,53.1 38.8,55.6 38.9,55.7 HDR1.61@38.9,60.5 HDR1.61@38.9,60.7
